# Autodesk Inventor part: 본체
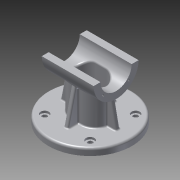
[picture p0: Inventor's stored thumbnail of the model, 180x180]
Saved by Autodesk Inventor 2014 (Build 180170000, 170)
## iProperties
Created: 2015-12
Part Number: 본체
Material: 알루미늄 6061
Document SubType Name: Modeling
Designer: mduedu
Density: 2.71 g/cm^3
Mass: 564.007 g
Surface Area: 536.242 cm^2
Volume: 208.121 cm^3
Appearance: 알루미늄 - 평지
Author: mduedu
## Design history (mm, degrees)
sketch "스케치1"
  geometry: L1 (45, 40)-(-45, 40); L2 (-45, 40)-(-45, -40); L3 (-45, -40)-(45, -40); L4 (45, -40)-(45, 40); L5 (45, 40)-(-45, -40); L6 (-45, 40)-(45, -40); 2 further points
  constraints: 12 end point, 2 midpoint, 2 parallel, 1 coincident, 1 horizontal, 1 perpendicular, 3 other
  dimensions: "d0" = 90 distance of L2.end L3.end; "d2" = 80 distance of L1.end L2.end
extrude "돌출1" new body sketch "스케치1" distance "d3" = 10; taper "d4" = 0 deg
sketch "스케치2"
  geometry: C1 r 32.5 at (80, 0); 1 further point
  constraints: 1 centre point
  dimensions: "d5" = 65 diameter of C1; "d116" = 80 distance of point (0, 0) C1.centre
extrude "돌출2" join sketch "스케치2" stored distance "d7" = 75; taper "d8" = 0 deg
sketch "스케치3"
  geometry: L1 (-27.5, -20)-(27.5, -20); L2 (27.5, -20)-(27.5, 20); L3 (27.5, 20)-(-27.5, 20); L4 (-27.5, 20)-(-27.5, -20); L5 (-27.5, -20)-(27.5, 20); L6 (27.5, -20)-(-27.5, 20); 1 further point
  constraints: 12 end point, 2 midpoint, 2 parallel, 1 horizontal, 1 perpendicular
  dimensions: "d9" = 55 distance of L2.end L3.end; "d11" = 40 distance of L1.end L2.end
extrude "돌출3" new body sketch "스케치3" stored distance "d12" = 75; taper "d13" = 0 deg
fillet "모깎기1"
fillet "모깎기2"
feature "결합1"
  node "솔리드2"
sketch "스케치4"
  geometry: L1 (-37.5, 47.5)-(37.5, 47.5) reference; L2 (32.5, 47.5)-(40.208, 10); L3 (37.5, 47.5)-(37.5, 112.5) reference; L4 (60.208, 0)-(60.208, 10) reference; L5 (60.208, 10)-(-60.208, 10) reference; 1 further point
  constraints: 2 end point, 2 point on line
  dimensions: "d15" = 5 distance from line of L2.start L3; "d117" = 20 distance from line of L2.end L4
sketch "스케치5"
  geometry: L1 (10, 35.208)-(58.179, 24.085); L2 (0, 60.208)-(10, 60.208) reference; L3 (10, -60.208)-(10, 60.208) reference; 2 further points
  constraints: 2 end point, 1 point on line, 2 other
  dimensions: "d118" = 25 distance from line of L1.start L2; "d119" = 77 deg angle of L1 L3
feature "리브1" dims "d19" = 1, "d20" = 6, "d21" = 0, "d22" = 0, "d23" = 1, "d24" = 1
feature "리브2" dims "d25" = 1, "d26" = 6, "d27" = 0, "d28" = 0, "d29" = 1, "d30" = 1
fillet "모깎기4" dims "d31" = 2
fillet "모깎기5" dims "d32" = 2
fillet "모깎기16" dims "d149" = 2
sketch "스케치6"
  geometry: L1 (0, 0)-(-32.88, 32.88); L2 (0, 0)-(-46.5, 0); A1 r 46.5 centre (0, 0) between (-32.88, 32.88) and (-46.5, 0); 5 further points
  constraints: 4 end point, 2 coincident, 2 point on circle, 1 centre point, 1 horizontal, 5 other
  dimensions: "d120" = 93 diameter of A1; "d122" = 45 deg angle of L1 L2; "d126" = 360 deg dimension on point (0, 0) point (-32.88, 32.88) (derived)
hole "구멍1" sketch "스케치6" at (-32.88, 32.88), (-32.88, -32.88), (32.88, -32.88), (32.88, 32.88) diameter "d34" = 7; stored, may be unused: countersink angle "d38" = 90 deg, drill point angle "d40" = 118 deg; dims "d35" = 6, "d36" = 12, "d37" = 3, "d39" = 8
fillet "모깎기13" dims "d131" = 3
hole "구멍2" diameter "d44" = 45; stored, may be unused: countersink angle "d48" = 90 deg, drill point angle "d50" = 118 deg; dims "d42" = 10, "d43" = 10, "d45" = 6, "d46" = 4, "d47" = 2, "d49" = 8
sketch "스케치7" dims "d52" = 26.5
  geometry: L1 (0, 0)-(32.5, 0); L2 (0, 0)-(22.981, 22.981); A1 r 32.5 centre (0, 0) between (32.5, 0) and (22.981, 22.981) reference; 3 further points
  constraints: 4 end point, 2 point on circle, 1 coincident, 1 horizontal, 1 point on line, 3 other
  dimensions: "d51" = 45 deg angle of L2 L1
hole "구멍3" sketch "스케치7" at (18.738, 18.738) diameter "d54" = 2.459; stored, may be unused: countersink angle "d58" = 90 deg, drill point angle "d60" = 118 deg; dims "d55" = 8, "d56" = 4, "d57" = 2, "d59" = 10
sketch "스케치9"
  geometry: L1 (-75, 82.5)-(75, 82.5); L2 (75, 82.5)-(75, 0); L3 (75, 0)-(-75, 0); L4 (-75, 0)-(-75, 82.5); C1 r 32.5 at (0, 0) reference; 2 further points
  constraints: 8 end point, 2 parallel, 1 coincident, 1 horizontal, 1 midpoint, 1 perpendicular
  dimensions: "d71" = 50 distance edge to line of C1 L1; "d148" = 150 distance of L1.start L1.end
extrude "돌출5" cut sketch "스케치9" stored distance "d73" = 0; taper "d74" = 0 deg
node "작업 평면1"
sketch "스케치10"
  geometry: L1 (-7.5, 15)-(7.5, 15); L2 (-7.5, -15)-(7.5, -15); A1 r 15 centre (-7.5, 0) between (-7.5, 15) and (-7.5, -15); A2 r 15 centre (7.5, 0) between (7.5, -15) and (7.5, 15); A3 r 20 centre (-7.5, 0) between (-7.5, 20) and (-26.977, 4.545) reference; A4 r 20 centre (7.5, 0) between (26.977, 4.545) and (7.5, 20) reference; 1 further point
  constraints: 7 point on circle, 4 end point, 4 tangent, 3 point on line, 2 centre point, 2 horizontal, 1 concentric
  dimensions: "d150" = 5 radial gap between concentric circles of A1 A3; "d151" = 5 radial gap between concentric circles of A2 A4
extrude "돌출6" cut sketch "스케치10" stored distance "d78" = 50; taper "d79" = 0 deg
fillet "모깎기10" dims "d80" = 3
sketch "스케치11"
  geometry: 2 further points
  constraints: 1 coincident
hole "구멍4" sketch "스케치11" at (0, 0) diameter "d81" = 11; stored, may be unused: countersink angle "d85" = 90 deg, drill point angle "d87" = 118 deg; dims "d82" = 8, "d83" = 40, "d84" = 10, "d86" = 10
sketch "스케치12"
  geometry: C1 r 12 at (0, 0); 1 further point
  constraints: 1 centre point, 1 coincident
  dimensions: "d88" = 24 diameter of C1
extrude "돌출7" cut sketch "스케치12" distance "d89" = 5; taper "d90" = 0 deg
chamfer "모따기1" distance "d91" = 1; stored, may be unused: second distance "d92" = 2, angle "d93" = 45 deg
fillet "모깎기11" dims "d94" = 0.5
fillet "모깎기12" dims "d115" = 0.3
node "작업 평면3"
sketch "스케치17"
  geometry: 2 further points
  constraints: 1 horizontal alignment, 1 other
  dimensions: "d154" = 3.5 distance of point (-3.5, 0) point (0, 0)
feature "엠보싱1" sketch "스케치17" dims "d155" = 0.5, "d156" = 0
node "솔리드1"
mirror "대칭1"
mirror "대칭2"
pattern_circular "원형 패턴1" dims angle "d62" = 360 deg
mirror "대칭3"
